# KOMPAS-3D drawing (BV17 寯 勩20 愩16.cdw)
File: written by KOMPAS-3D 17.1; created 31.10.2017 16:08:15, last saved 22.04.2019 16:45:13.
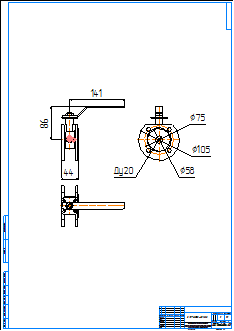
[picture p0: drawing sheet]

Sheet 1: A1, portrait

Title block, sheet 1: name: BV17 МФ Ду20 Ру16; material: Внимание! Данный продукт является объектом авторского права ООО «Торговый Дом АДЛ». / Запрещается изменение, копирование, распространение / (в том числе путем копирования на другие сайты и ресурсы в Интернете) / или любое иное использование информации и объектов без предварительного / согласия правообладателя (ООО «Торговый Дом АДЛ»).; mass: 1; sheets: 1; organisation: ООО "Торговый дом АДЛ"; sheet format: A1; stored path: \\adlc.lan\data\АДЛ_ПКД\3D-модели\ADL production\Краны шаровые серии BV\BV17 МФ Нержавеющие Ру16\KOMPAS 2D\BV17 МФ Ду20 Ру16.cdw

Views: Вид 1, Проекционный вид 2, Проекционный вид 3
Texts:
  kka
  adl
Dimensions and other numbers on the sheet: 44; 141; 86; 20; 105; 75; 58; 1:1; 1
